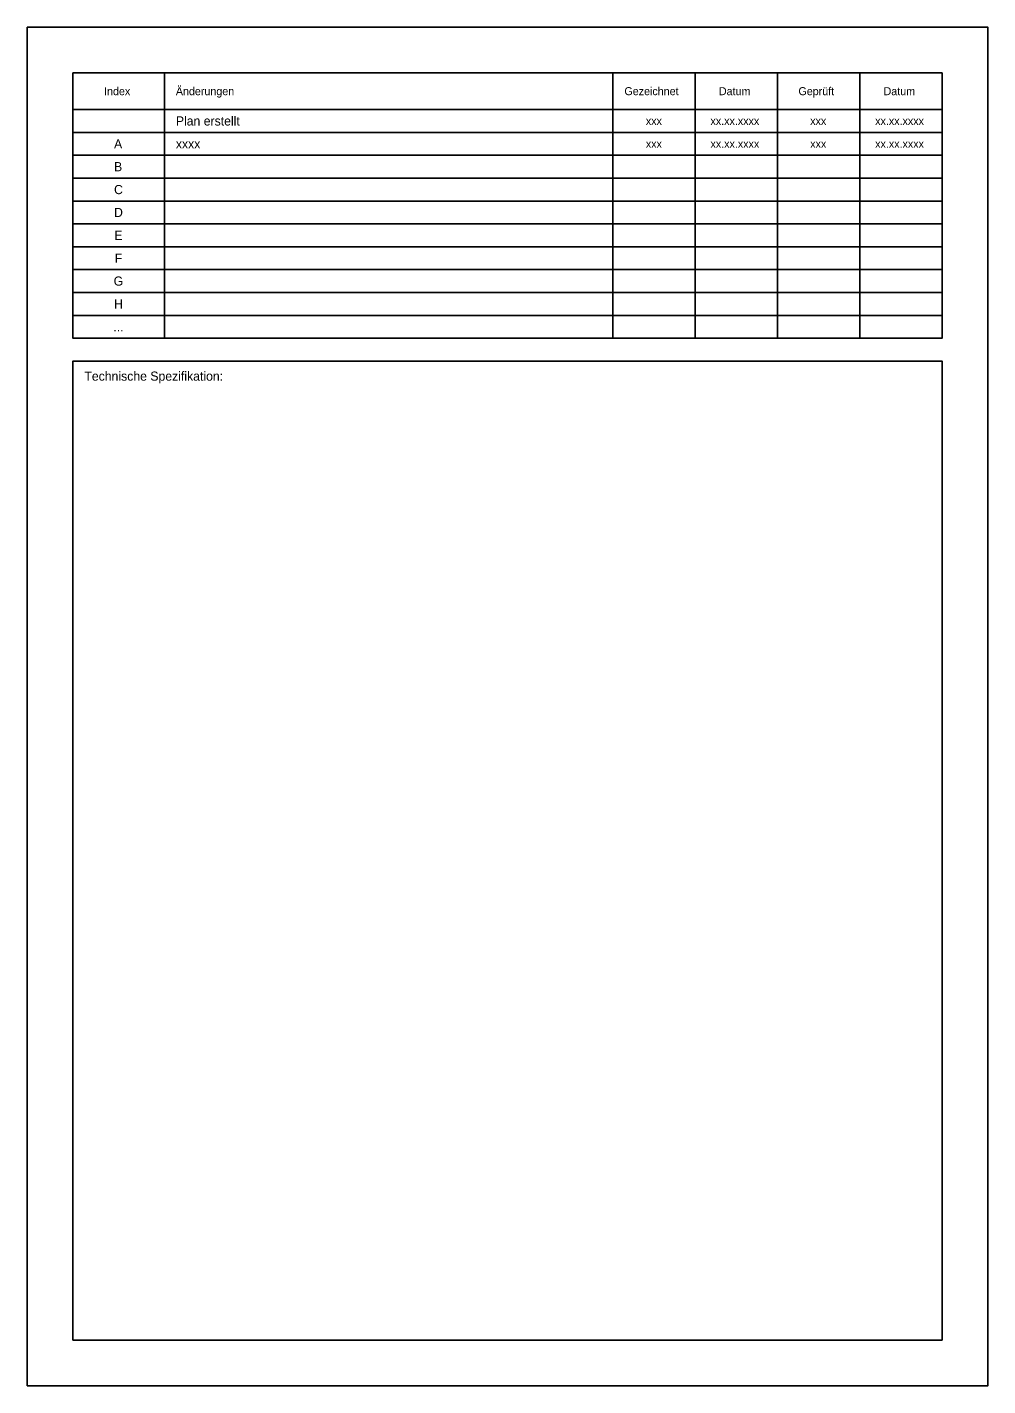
# Model space of a CAD drawing. Extents: x 0 to 443, y 0 to 297.
# Drawn here: x 232.7 to 442.7, y 0 to 297 of the extents above; entities that cross this region are included whole.
import ezdxf

# ---------------------------------------------------------------- set-up
doc = ezdxf.new("R2010")
doc.units = 0
doc.layers.add('A_Titel', color=7, linetype='Continuous')
doc.layers.add('HILFSKONSTR', color=7, linetype='Continuous')

msp = doc.modelspace()

# ---------------------------------------------------------------- linework, layer by layer
at = {"layer": 'A_Titel'}
for p, q in [((360.75, 287), (360.75, 229)), ((378.75, 287), (378.75, 229)), ((396.75, 287), (396.75, 229)), ((414.75, 287), (414.75, 229))]:
    msp.add_line(p, q, dxfattribs=at)
for points in [[(232.75, 297), (442.75, 297), (442.75, 0), (232.75, 0)], [(242.75, 287), (432.75, 287), (432.75, 229), (242.75, 229)]]:
    msp.add_lwpolyline(points, close=True, dxfattribs=at)
for points in [[(262.75, 287), (262.75, 229)], [(432.75, 287), (432.75, 229)], [(242.75, 279), (432.75, 279)], [(242.75, 274), (432.75, 274)], [(242.75, 269), (432.75, 269)], [(242.75, 264), (432.75, 264)], [(242.75, 259), (432.75, 259)], [(242.75, 254), (432.75, 254)], [(242.75, 249), (432.75, 249)], [(242.75, 244), (432.75, 244)], [(242.75, 239), (432.75, 239)], [(242.75, 234), (432.75, 234)], [(242.75, 10), (432.75, 10), (432.75, 224), (242.75, 224), (242.75, 10)]]:
    msp.add_lwpolyline(points, dxfattribs=at)

# ---------------------------------------------------------------- texts
for s, height, p in [('Index', 1.75, (249.56, 282.13)), ('Änderungen', 1.75, (265.25, 282.13)), ('Gezeichnet', 1.75, (363.31, 282.13)), ('Datum', 1.75, (383.96, 282.13)), ('Geprüft', 1.75, (401.35, 282.13)), ('Datum', 1.75, (419.96, 282.13)), ('Plan erstellt', 2, (265.25, 275.5)), ('xxx', 1.75, (367.99, 275.63)), ('xx.xx.xxxx', 1.75, (382.12, 275.63)), ('xxx', 1.75, (403.92, 275.63)), ('xx.xx.xxxx', 1.75, (418.12, 275.63)), ('A', 2, (251.74, 270.5)), ('xxxx', 2, (265.25, 270.5)), ('B', 2, (251.74, 265.5)), ('C', 2, (251.74, 260.5)), ('D', 2, (251.74, 255.5)), ('E', 2, (251.82, 250.5)), ('F', 2, (251.89, 245.5)), ('G', 2, (251.66, 240.5)), ('H', 2, (251.74, 235.5)), ('...', 2, (251.58, 230.5)), ('Technische Spezifikation:', 2, (245.25, 219.72))]:
    msp.add_text(s, height=height, dxfattribs=at).set_placement(p)
at = {"layer": 'HILFSKONSTR'}
for s, p in [('xxx', (367.99, 270.63)), ('xx.xx.xxxx', (382.12, 270.63)), ('xxx', (403.92, 270.63)), ('xx.xx.xxxx', (418.12, 270.63))]:
    msp.add_text(s, height=1.75, dxfattribs=at).set_placement(p)

doc.saveas('drawing.dxf')
